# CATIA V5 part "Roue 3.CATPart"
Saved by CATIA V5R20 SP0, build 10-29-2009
Part number: roue 3
Bounding box of the stored display mesh (mm): x -50 to 50, y -50 to 50, z -5 to 25
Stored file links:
  E:\EDELI\wjacquemont\Edeli_2012_122_wjacquemont\Roue 3.CATPart
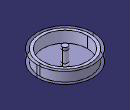
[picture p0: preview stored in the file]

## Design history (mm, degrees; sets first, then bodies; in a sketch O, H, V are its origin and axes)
Body1 (main body)
  Sketch1 on xy-plane, origin (0, 0, 0), H (1, 0, 0), V (0, 1, 0)
    circle A1 centre (0, 0) radius 5
    circle A2 centre (0, 0) radius 40
    radius A1 = 5
    radius A2 = 40
  Pad1: profile Sketch1, direction (0, 0, 1), length 20
Body2
  Sketch2 on end face of Pad1, origin (0, 0, 20), H (1, 0, 0), V (0, 1, 0)
    circle A1 centre (0, 0) radius 45
    circle A2 centre (0, 0) radius 40
    reference projected circle E1 centre (0, 0) radius 40 from edge [face of Pad1 from Sketch1.A2 | end face of Pad1]
    radius A1 = 45
    coincidence: E1 A2
  Pad2: profile Sketch2, direction (0, 0, -1), length 20
Body3
  Sketch3 on end face of Pad1, origin (0, 0, 20), H (1, 0, 0), V (0, 1, 0)
    circle A1 centre (0, 0) radius 50
    circle A2 centre (0, 0) radius 45
    reference projected circle E1 centre (0, 0) radius 45 from edge [face of Pad2 from Sketch2.A1 | start face of Pad2]
    radius A1 = 50
    coincidence: E1 A2
  Pad3: profile Sketch3, direction (0, 0, -1), length 20
  DatumCurve1
  Sketch4 on end face of Pad1, origin (0, 0, 20), H (1, 0, 0), V (0, 1, 0)
    circle A1 centre (0, 0) radius 5
    reference projected circle E1 centre (0, 0) radius 5 from edge of DatumCurve1
    coincidence: E1 A1
  Pad4: profile Sketch4, direction (0, 0, 1), length 5, opposite side length 25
